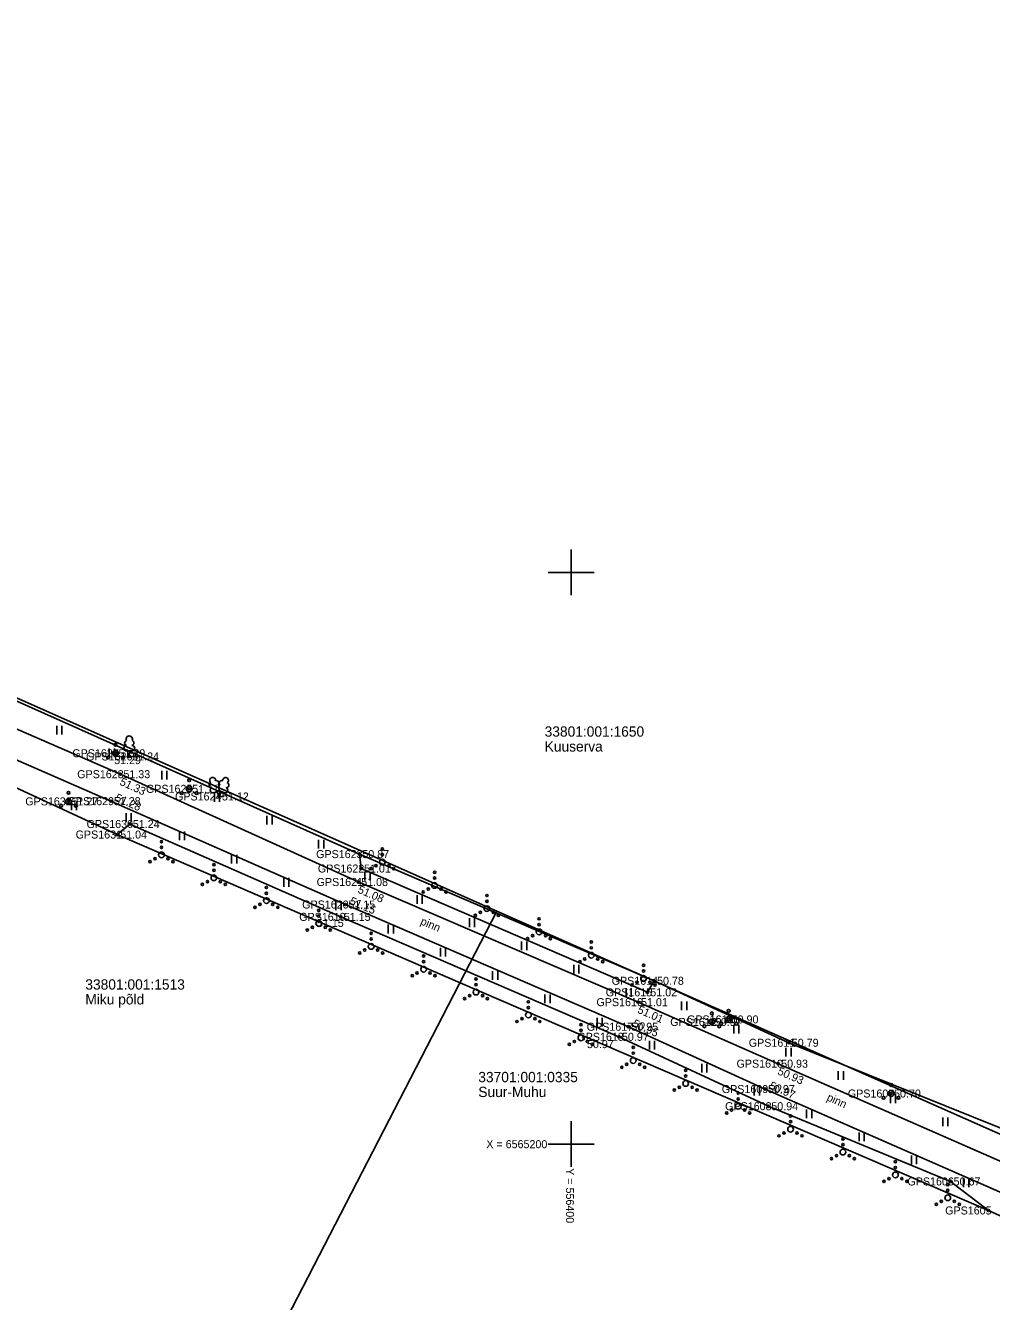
# Model space of a CAD drawing. Extents: x 551623 to 559850, y 6561220 to 6567135.
# Drawn here: x 556352.3 to 556436.7, y 6565186.2 to 6565297.8 of the extents above; entities that cross this region are included whole.
import ezdxf

# ---------------------------------------------------------------- set-up
doc = ezdxf.new("R2010")
doc.units = 0
for name, color, linetype in [('HALJASTUS', 7, 'Continuous'), ('KORGUS-EH2000', 7, 'Continuous'), ('MOOTKORG-EH2000', 7, 'Continuous'), ('MOOTMPUNKT', 7, 'Continuous'), ('MOOTNR', 7, 'Continuous'), ('MOOTPIIR', 7, 'Continuous'), ('PIIR', 7, 'Continuous'), ('PUU', 7, 'Continuous'), ('TEE', 7, 'Continuous'), ('VORK', 7, 'Continuous')]:
    doc.layers.add(name, color=color, linetype=linetype)

msp = doc.modelspace()

# ---------------------------------------------------------------- linework, layer by layer
at = {"layer": 'HALJASTUS'}
for p, q in [((556355.02, 6565236.58), (556355.02, 6565235.82)), ((556355.47, 6565236.58), (556355.47, 6565235.82)), ((556359.61, 6565234.61), (556359.61, 6565233.85)), ((556360.07, 6565234.61), (556360.07, 6565233.85)), ((556364.21, 6565232.64), (556364.21, 6565231.88)), ((556364.66, 6565232.64), (556364.66, 6565231.88)), ((556368.81, 6565230.68), (556368.81, 6565229.92)), ((556369.26, 6565230.68), (556369.26, 6565229.92)), ((556356.31, 6565229.95), (556356.31, 6565229.19)), ((556356.76, 6565229.95), (556356.76, 6565229.19)), ((556361.08, 6565228.95), (556361.08, 6565228.19)), ((556361.53, 6565228.95), (556361.53, 6565228.19)), ((556373.4, 6565228.71), (556373.4, 6565227.95)), ((556373.86, 6565228.71), (556373.86, 6565227.95)), ((556365.74, 6565227.34), (556365.74, 6565226.58)), ((556366.19, 6565227.34), (556366.19, 6565226.58)), ((556377.9, 6565226.6), (556377.9, 6565225.84)), ((556378.36, 6565226.6), (556378.36, 6565225.84)), ((556370.3, 6565225.3), (556370.3, 6565224.54)), ((556370.76, 6565225.3), (556370.76, 6565224.54)), ((556381.96, 6565223.82), (556381.96, 6565223.06)), ((556382.42, 6565223.82), (556382.42, 6565223.06)), ((556374.87, 6565223.27), (556374.87, 6565222.5)), ((556375.32, 6565223.27), (556375.32, 6565222.5)), ((556386.53, 6565221.78), (556386.53, 6565221.02)), ((556386.98, 6565221.78), (556386.98, 6565221.02)), ((556379.43, 6565221.23), (556379.43, 6565220.47)), ((556379.89, 6565221.23), (556379.89, 6565220.47)), ((556384, 6565219.19), (556384, 6565218.43)), ((556384.46, 6565219.19), (556384.46, 6565218.43)), ((556391.1, 6565219.75), (556391.1, 6565218.98)), ((556391.55, 6565219.75), (556391.55, 6565218.98)), ((556388.57, 6565217.15), (556388.57, 6565216.39)), ((556389.02, 6565217.15), (556389.02, 6565216.39)), ((556395.66, 6565217.71), (556395.66, 6565216.95)), ((556396.12, 6565217.71), (556396.12, 6565216.95)), ((556393.13, 6565215.12), (556393.13, 6565214.36)), ((556393.59, 6565215.12), (556393.59, 6565214.36)), ((556400.23, 6565215.67), (556400.23, 6565214.91)), ((556400.68, 6565215.67), (556400.68, 6565214.91)), ((556404.8, 6565213.64), (556404.8, 6565212.88)), ((556405.25, 6565213.64), (556405.25, 6565212.88)), ((556397.7, 6565213.08), (556397.7, 6565212.32)), ((556398.15, 6565213.08), (556398.15, 6565212.32)), ((556409.64, 6565212.47), (556409.64, 6565211.71)), ((556410.1, 6565212.47), (556410.1, 6565211.71)), ((556402.27, 6565211.04), (556402.27, 6565210.28)), ((556402.72, 6565211.04), (556402.72, 6565210.28)), ((556414.21, 6565210.44), (556414.21, 6565209.68)), ((556414.67, 6565210.44), (556414.67, 6565209.68)), ((556406.84, 6565209.02), (556406.84, 6565208.26)), ((556407.29, 6565209.02), (556407.29, 6565208.26)), ((556418.78, 6565208.41), (556418.78, 6565207.65)), ((556419.24, 6565208.41), (556419.24, 6565207.65)), ((556411.42, 6565207.02), (556411.42, 6565206.26)), ((556411.87, 6565207.02), (556411.87, 6565206.26)), ((556423.35, 6565206.38), (556423.35, 6565205.62)), ((556423.81, 6565206.38), (556423.81, 6565205.62)), ((556416, 6565205.02), (556416, 6565204.26)), ((556416.46, 6565205.02), (556416.46, 6565204.26)), ((556427.92, 6565204.35), (556427.92, 6565203.59)), ((556428.37, 6565204.35), (556428.37, 6565203.59)), ((556420.58, 6565203.02), (556420.58, 6565202.25)), ((556421.04, 6565203.02), (556421.04, 6565202.25)), ((556432.49, 6565202.32), (556432.49, 6565201.56)), ((556432.94, 6565202.32), (556432.94, 6565201.56)), ((556425.17, 6565201.01), (556425.17, 6565200.25)), ((556425.62, 6565201.01), (556425.62, 6565200.25)), ((556429.75, 6565199.01), (556429.75, 6565198.25)), ((556430.2, 6565199.01), (556430.2, 6565198.25)), ((556434.31, 6565196.98), (556434.31, 6565196.22)), ((556434.77, 6565196.98), (556434.77, 6565196.22))]:
    msp.add_line(p, q, dxfattribs=at)
for points in [[(556360.31, 6565227.07), (556361.41, 6565227.99), (556379.86, 6565219.87), (556404.18, 6565209.38), (556417.24, 6565203.31), (556433.18, 6565196.73), (556436.48, 6565194.19)], [(556381.48, 6565225.36), (556381.63, 6565224.1), (556406.66, 6565213.27), (556407.25, 6565214.28)]]:
    msp.add_lwpolyline(points, dxfattribs=at)
for centre, radius in [((556364.18, 6565226.44), 0.1), ((556364.18, 6565225.94), 0.1), ((556383.49, 6565225.81), 0.1), ((556363.18, 6565224.71), 0.1), ((556363.62, 6565224.96), 0.1), ((556364.18, 6565225.29), 0.25), ((556364.75, 6565224.96), 0.1), ((556365.18, 6565224.71), 0.1), ((556383.49, 6565224.66), 0.25), ((556383.49, 6565225.31), 0.1), ((556368.76, 6565224.44), 0.1), ((556368.76, 6565223.94), 0.1), ((556382.49, 6565224.09), 0.1), ((556382.93, 6565224.34), 0.1), ((556384.06, 6565224.34), 0.1), ((556384.49, 6565224.09), 0.1), ((556388.06, 6565223.77), 0.1), ((556367.76, 6565222.71), 0.1), ((556368.2, 6565222.96), 0.1), ((556368.76, 6565223.29), 0.25), ((556369.33, 6565222.96), 0.1), ((556369.76, 6565222.71), 0.1), ((556373.35, 6565222.44), 0.1), ((556388.06, 6565222.62), 0.25), ((556388.06, 6565223.27), 0.1), ((556373.35, 6565221.29), 0.25), ((556373.35, 6565221.94), 0.1), ((556387.06, 6565222.05), 0.1), ((556387.5, 6565222.3), 0.1), ((556388.63, 6565222.3), 0.1), ((556389.06, 6565222.05), 0.1), ((556392.63, 6565221.74), 0.1), ((556392.63, 6565221.24), 0.1), ((556372.35, 6565220.71), 0.1), ((556372.78, 6565220.96), 0.1), ((556373.91, 6565220.96), 0.1), ((556374.35, 6565220.71), 0.1), ((556377.93, 6565220.44), 0.1), ((556392.06, 6565220.26), 0.1), ((556392.63, 6565220.59), 0.25), ((556393.19, 6565220.26), 0.1), ((556377.93, 6565219.29), 0.25), ((556377.93, 6565219.94), 0.1), ((556391.63, 6565220.01), 0.1), ((556393.63, 6565220.01), 0.1), ((556397.19, 6565219.7), 0.1), ((556397.19, 6565219.2), 0.1), ((556376.93, 6565218.71), 0.1), ((556377.37, 6565218.96), 0.1), ((556378.5, 6565218.96), 0.1), ((556378.93, 6565218.71), 0.1), ((556382.51, 6565218.44), 0.1), ((556382.51, 6565217.94), 0.1), ((556396.19, 6565217.97), 0.1), ((556396.63, 6565218.22), 0.1), ((556397.19, 6565218.55), 0.25), ((556397.76, 6565218.22), 0.1), ((556398.19, 6565217.97), 0.1), ((556381.95, 6565216.97), 0.1), ((556382.51, 6565217.29), 0.25), ((556383.08, 6565216.97), 0.1), ((556401.76, 6565217.66), 0.1), ((556401.76, 6565217.16), 0.1), ((556381.51, 6565216.72), 0.1), ((556383.51, 6565216.72), 0.1), ((556387.1, 6565216.44), 0.1), ((556387.1, 6565215.94), 0.1), ((556400.76, 6565215.94), 0.1), ((556401.19, 6565216.19), 0.1), ((556401.76, 6565216.51), 0.25), ((556402.32, 6565216.19), 0.1), ((556402.76, 6565215.94), 0.1), ((556386.1, 6565214.72), 0.1), ((556386.53, 6565214.97), 0.1), ((556387.1, 6565215.29), 0.25), ((556387.66, 6565214.97), 0.1), ((556388.1, 6565214.72), 0.1), ((556406.33, 6565214.48), 0.25), ((556406.33, 6565215.63), 0.1), ((556406.33, 6565215.13), 0.1), ((556391.68, 6565213.29), 0.25), ((556391.68, 6565214.44), 0.1), ((556391.68, 6565213.94), 0.1), ((556405.33, 6565213.9), 0.1), ((556405.76, 6565214.15), 0.1), ((556406.89, 6565214.15), 0.1), ((556407.33, 6565213.9), 0.1), ((556390.68, 6565212.72), 0.1), ((556391.12, 6565212.97), 0.1), ((556392.25, 6565212.97), 0.1), ((556392.68, 6565212.72), 0.1), ((556396.26, 6565212.44), 0.1), ((556396.26, 6565211.29), 0.25), ((556396.26, 6565211.94), 0.1), ((556395.26, 6565210.72), 0.1), ((556395.7, 6565210.97), 0.1), ((556396.83, 6565210.97), 0.1), ((556397.26, 6565210.72), 0.1), ((556400.85, 6565210.44), 0.1), ((556400.28, 6565208.97), 0.1), ((556400.85, 6565209.29), 0.25), ((556400.85, 6565209.94), 0.1), ((556401.41, 6565208.97), 0.1), ((556399.85, 6565208.72), 0.1), ((556401.85, 6565208.72), 0.1), ((556405.43, 6565208.45), 0.1), ((556405.43, 6565207.95), 0.1), ((556404.86, 6565206.97), 0.1), ((556405.43, 6565207.3), 0.25), ((556405.99, 6565206.97), 0.1), ((556404.43, 6565206.72), 0.1), ((556406.43, 6565206.72), 0.1), ((556410.01, 6565206.45), 0.1), ((556410.01, 6565205.95), 0.1), ((556409.01, 6565204.72), 0.1), ((556409.45, 6565204.97), 0.1), ((556410.01, 6565205.3), 0.25), ((556410.58, 6565204.97), 0.1), ((556411.01, 6565204.72), 0.1), ((556414.6, 6565203.3), 0.25), ((556414.6, 6565204.45), 0.1), ((556414.6, 6565203.95), 0.1), ((556413.6, 6565202.72), 0.1), ((556414.03, 6565202.97), 0.1), ((556415.16, 6565202.97), 0.1), ((556415.6, 6565202.72), 0.1), ((556419.18, 6565202.45), 0.1), ((556419.18, 6565201.3), 0.25), ((556419.18, 6565201.95), 0.1), ((556418.18, 6565200.72), 0.1), ((556418.61, 6565200.97), 0.1), ((556419.74, 6565200.97), 0.1), ((556420.18, 6565200.72), 0.1), ((556423.76, 6565200.45), 0.1), ((556423.2, 6565198.98), 0.1), ((556423.76, 6565199.3), 0.25), ((556423.76, 6565199.95), 0.1), ((556424.33, 6565198.98), 0.1), ((556422.76, 6565198.73), 0.1), ((556424.76, 6565198.73), 0.1), ((556428.35, 6565198.45), 0.1), ((556428.35, 6565197.95), 0.1), ((556427.35, 6565196.73), 0.1), ((556427.78, 6565196.98), 0.1), ((556428.35, 6565197.3), 0.25), ((556428.91, 6565196.98), 0.1), ((556429.35, 6565196.73), 0.1), ((556432.93, 6565196.45), 0.1), ((556432.93, 6565195.95), 0.1), ((556431.93, 6565194.73), 0.1), ((556432.36, 6565194.98), 0.1), ((556432.93, 6565195.3), 0.25), ((556433.49, 6565194.98), 0.1), ((556433.93, 6565194.73), 0.1)]:
    msp.add_circle(centre, radius, dxfattribs=at)
at = {"layer": 'KORGUS-EH2000'}
for centre in [(556360.16, 6565234.18), (556360.59, 6565232.35), (556359.75, 6565229.99), (556360.31, 6565227.07), (556381.48, 6565225.36), (556381.38, 6565222.92), (556380.26, 6565220.95), (556379.86, 6565219.87), (556407.25, 6565214.28), (556405.85, 6565212.41), (556405, 6565210.26), (556404.18, 6565209.38), (556419.03, 6565208.86), (556418.1, 6565207.03), (556416.95, 6565204.81), (556417.24, 6565203.31), (556436.48, 6565194.19)]:
    msp.add_circle(centre, 0.1, dxfattribs=at)
at = {"layer": 'MOOTMPUNKT'}
for centre in [(556360.16, 6565234.18), (556361.36, 6565233.9), (556360.59, 6565232.35), (556366.6, 6565231.07), (556369.21, 6565230.4), (556356.05, 6565229.97), (556359.75, 6565229.99), (556361.41, 6565227.99), (556360.31, 6565227.07), (556381.48, 6565225.36), (556381.63, 6565224.1), (556381.38, 6565222.92), (556380.26, 6565220.95), (556379.86, 6565219.87), (556407.25, 6565214.28), (556405.85, 6565212.41), (556406.66, 6565213.27), (556405, 6565210.26), (556412.3, 6565210.68), (556413.77, 6565210.9), (556404.18, 6565209.38), (556419.03, 6565208.86), (556418.1, 6565207.03), (556416.95, 6565204.81), (556427.97, 6565204.42), (556417.24, 6565203.31), (556433.18, 6565196.73), (556436.48, 6565194.19)]:
    msp.add_circle(centre, 0.1, dxfattribs=at)
at = {"layer": 'MOOTPIIR'}
for points in [[(556444.3, 6565198.68), (556419.03, 6565208.86), (556407.25, 6565214.28), (556381.48, 6565225.36), (556332.64, 6565247.15), (556319.44, 6565253.29), (556278.3, 6565271.26)], [(556293.31, 6565257.46), (556317.81, 6565246.71), (556360.31, 6565227.07), (556390.3, 6565214.09), (556436.48, 6565194.19), (556449.65, 6565188.22)]]:
    msp.add_lwpolyline(points, dxfattribs=at)
at = {"layer": 'PIIR'}
for points in [[(556217.39, 6565298.59), (556213.87, 6565303.19), (556229.81, 6565311.25), (556335.44, 6565331.24), (556350.73, 6565342.07), (556507.54, 6565334), (556519.21, 6565368.05), (556548.5, 6565368.1), (556612.15, 6565380.04), (556615.14, 6565380.2), (556613.56, 6565366.23), (556611.32, 6565356.67), (556591.74, 6565273.2), (556570.09, 6565180.67), (556561.87, 6565145.74), (556557.67, 6565147.61), (556393.49, 6565220.36)], [(556206.35, 6565280.04), (556217.39, 6565298.59), (556393.49, 6565220.36), (556274.8, 6564990.28), (556228.34, 6565008.72), (556105.05, 6565057.69), (556140.52, 6565135.89), (556229.38, 6565104.35), (556274.08, 6565194.99), (556184.08, 6565232.1), (556196.52, 6565258.88), (556203.12, 6565272.11)], [(556393.49, 6565220.36), (556557.67, 6565147.61), (556561.87, 6565145.74), (556518.27, 6565016.8), (556485.25, 6564921.4), (556406.78, 6564699.5), (556400.89, 6564700.63), (556129.6, 6564752.43), (556228.34, 6565008.72), (556274.8, 6564990.28)]]:
    msp.add_lwpolyline(points, close=True, dxfattribs=at)
at = {"layer": 'PUU'}
for p, q in [((556361.6, 6565234.38), (556361.12, 6565234.38)), ((556361.36, 6565233.9), (556361.36, 6565234.38)), ((556361.74, 6565233.9), (556361.36, 6565233.9)), ((556368.77, 6565230.73), (556369.21, 6565230.91)), ((556369.21, 6565230.4), (556369.03, 6565230.84)), ((556369.21, 6565230.91), (556369.65, 6565230.73)), ((556369.21, 6565230.4), (556369.39, 6565230.84)), ((556369.59, 6565230.4), (556369.21, 6565230.4))]:
    msp.add_line(p, q, dxfattribs=at)
msp.add_lwpolyline([(556369.21, 6565231.4), (556369.19, 6565231.33), (556369.19, 6565231.31), (556369.2, 6565231.28), (556369.22, 6565231.24), (556369.23, 6565231.22), (556369.21, 6565231.19), (556369.19, 6565231.14), (556369.18, 6565231.11), (556369.19, 6565231.1), (556369.2, 6565231.07), (556369.23, 6565231.01), (556369.24, 6565230.99), (556369.23, 6565230.97), (556369.22, 6565230.93), (556369.21, 6565230.91)], dxfattribs=at)
for centre, radius in [((556360.16, 6565234.93), 0.125), ((556359.51, 6565233.81), 0.125), ((556360.16, 6565234.18), 0.25), ((556360.81, 6565233.81), 0.125), ((556366.6, 6565231.82), 0.125), ((556356.05, 6565230.72), 0.125), ((556365.95, 6565230.69), 0.125), ((556366.6, 6565231.07), 0.25), ((556367.25, 6565230.69), 0.125), ((556355.4, 6565229.59), 0.125), ((556356.05, 6565229.97), 0.25), ((556356.7, 6565229.59), 0.125), ((556412.3, 6565211.43), 0.125), ((556413.77, 6565211.65), 0.125), ((556411.65, 6565210.3), 0.125), ((556412.3, 6565210.68), 0.25), ((556412.95, 6565210.3), 0.125), ((556413.12, 6565210.53), 0.125), ((556413.77, 6565210.9), 0.25), ((556414.42, 6565210.53), 0.125), ((556427.97, 6565204.42), 0.25), ((556427.97, 6565205.17), 0.125), ((556427.32, 6565204.04), 0.125), ((556428.62, 6565204.04), 0.125)]:
    msp.add_circle(centre, radius, dxfattribs=at)
for centre, radius, start, end in [((556361.12, 6565234.62), 0.238, 90.0016, 269.3953), ((556361.19, 6565235.08), 0.233, 109.0217, 253.1415), ((556361.36, 6565235.42), 0.277, 332.5799, 207.4201), ((556361.53, 6565235.08), 0.233, 286.8508, 70.9859), ((556361.6, 6565234.62), 0.238, 270.6047, 89.9984), ((556368.57, 6565231.4), 0.224, 111.4304, 274.4987), ((556368.65, 6565231.81), 0.256, 111.5027, 232.5173), ((556368.65, 6565231.81), 0.256, 350.4856, 111.5002), ((556368.98, 6565231.56), 0.224, 308.5041, 111.5725), ((556369.21, 6565231.17), 0.237, 66.7655, 111.5015), ((556369.45, 6565231.56), 0.225, 67.7016, 230.5126), ((556369.78, 6565231.8), 0.256, 67.6168, 188.6314), ((556369.85, 6565231.39), 0.224, 264.6183, 67.6866), ((556369.78, 6565231.8), 0.256, 306.5997, 67.6143), ((556368.68, 6565230.96), 0.237, 111.5014, 291.5004), ((556369.74, 6565230.95), 0.237, 247.6166, 67.6155)]:
    msp.add_arc(centre, radius, start, end, dxfattribs=at)
at = {"layer": 'TEE'}
for points in [[(556212.52, 6565297.66), (556233.2, 6565288.81), (556257.43, 6565277.89), (556277.38, 6565268.88), (556295.26, 6565260.97), (556307.22, 6565255.62), (556319.32, 6565250.22), (556331.63, 6565244.87), (556340.73, 6565240.97), (556360.59, 6565232.35), (556381.38, 6565222.92), (556405.85, 6565212.41), (556418.1, 6565207.03), (556442.44, 6565196.36)], [(556563.78, 6565138.67), (556560.87, 6565140.85), (556553.17, 6565143.6), (556545.59, 6565147.01), (556535.18, 6565151.57), (556522.84, 6565156.96), (556502.18, 6565166.78), (556486.19, 6565174.09), (556471.01, 6565180.89), (556450.06, 6565190.45), (556440.99, 6565194.27), (556416.95, 6565204.81), (556405, 6565210.26), (556380.26, 6565220.95), (556359.75, 6565229.99), (556339.78, 6565238.7), (556330.66, 6565242.67), (556318.5, 6565248.07), (556306, 6565253.52), (556294.08, 6565258.94), (556276.19, 6565266.76), (556256.29, 6565275.58), (556232.17, 6565286.79), (556209.59, 6565295.96)]]:
    msp.add_lwpolyline(points, dxfattribs=at)
at = {"layer": 'VORK'}
for p, q in [((556400, 6565252), (556400, 6565248)), ((556398, 6565250), (556402, 6565250)), ((556400, 6565202), (556400, 6565198)), ((556398, 6565200), (556402, 6565200))]:
    msp.add_line(p, q, dxfattribs=at)

# ---------------------------------------------------------------- texts
at = {"layer": 'KORGUS-EH2000'}
for s, p in [(' 51.29', (556359.78, 6565233.23)), (' 51.04', (556360.31, 6565226.72)), (' 50.87', (556381.48, 6565225.01)), (' 51.15', (556377.51, 6565218.99)), (' 50.78', (556407.25, 6565213.93)), (' 50.97', (556401.12, 6565208.39)), (' 50.79', (556419.03, 6565208.51)), (' 50.94', (556417.24, 6565202.96))]:
    msp.add_text(s, height=0.7, dxfattribs=at).set_placement(p)
for s, rotation, p in [(' 51.33', 335.6082, (556360.23, 6565231.55)), (' 51.28', 336.2267, (556359.82, 6565230.15)), (' 51.08', 336.7632, (556381.04, 6565222.11)), (' 51.15', 336.6287, (556380.33, 6565221.11)), (' 51.01', 336.2742, (556405.5, 6565211.61)), (' 50.95', 335.4708, (556405.07, 6565210.42)), (' 50.93', 336.343, (556417.75, 6565206.23)), (' 50.97', 336.3229, (556417.02, 6565204.97))]:
    msp.add_text(s, height=0.7, rotation=rotation, dxfattribs=at).set_placement(p)
at = {"layer": 'MOOTKORG-EH2000'}
for s, p in [(' 51.29', (556360.16, 6565233.83)), (' 51.24', (556361.36, 6565233.55)), (' 51.33', (556360.59, 6565232)), (' 51.11', (556366.6, 6565230.72)), (' 51.27', (556356.05, 6565229.62)), (' 51.28', (556359.75, 6565229.64)), (' 51.12', (556369.21, 6565230.05)), (' 51.24', (556361.41, 6565227.64)), (' 51.04', (556360.31, 6565226.72)), (' 50.87', (556381.48, 6565225.01)), (' 51.01', (556381.63, 6565223.75)), (' 51.08', (556381.38, 6565222.57)), (' 51.15', (556379.86, 6565219.52)), (' 51.15', (556380.26, 6565220.6)), (' 50.78', (556407.25, 6565213.93)), (' 51.02', (556406.66, 6565212.92)), (' 51.01', (556405.85, 6565212.06)), (' 50.95', (556405, 6565209.91)), (' 50.97', (556412.3, 6565210.33)), (' 50.90', (556413.77, 6565210.55)), (' 50.97', (556404.18, 6565209.03)), (' 50.79', (556419.03, 6565208.51)), (' 50.93', (556418.1, 6565206.68)), (' 50.97', (556416.95, 6565204.46)), (' 50.70', (556427.97, 6565204.07)), (' 50.94', (556417.24, 6565202.96)), (' 50.67', (556433.18, 6565196.38))]:
    msp.add_text(s, height=0.7, dxfattribs=at).set_placement(p)
at = {"layer": 'MOOTNR'}
for s, p in [('GPS1627 ', (556356.38, 6565233.83)), ('GPS1626 ', (556357.58, 6565233.55)), ('GPS1628 ', (556356.81, 6565232)), ('GPS1625 ', (556362.82, 6565230.72)), ('GPS1632 ', (556352.27, 6565229.62)), ('GPS1629 ', (556355.97, 6565229.64)), ('GPS1624 ', (556365.36, 6565230.05)), ('GPS1630 ', (556357.63, 6565227.64)), ('GPS1631 ', (556356.67, 6565226.72)), ('GPS1623 ', (556377.7, 6565225.01)), ('GPS1622 ', (556377.85, 6565223.75)), ('GPS1621 ', (556377.74, 6565222.57)), ('GPS1619 ', (556376.22, 6565219.52)), ('GPS1620 ', (556376.48, 6565220.6)), ('GPS1614 ', (556403.54, 6565213.93)), ('GPS1615 ', (556403.02, 6565212.92)), ('GPS1616 ', (556402.21, 6565212.06)), ('GPS1617 ', (556401.36, 6565209.91)), ('GPS1612 ', (556408.66, 6565210.33)), ('GPS1613 ', (556410.13, 6565210.55)), ('GPS1618 ', (556400.54, 6565209.03)), ('GPS1611 ', (556415.53, 6565208.51)), ('GPS1610 ', (556414.46, 6565206.68)), ('GPS1609 ', (556413.17, 6565204.46)), ('GPS1607 ', (556424.19, 6565204.07)), ('GPS1608 ', (556413.46, 6565202.96)), ('GPS1606 ', (556429.4, 6565196.38)), ('GPS1605 ', (556432.7, 6565193.84))]:
    msp.add_text(s, height=0.7, dxfattribs=at).set_placement(p)
at = {"layer": 'PIIR'}
for s, p in [('33801:001:1650', (556397.68, 6565235.63)), ('Kuuserva', (556397.68, 6565234.33)), ('33801:001:1513', (556357.52, 6565213.51)), ('Miku põld', (556357.52, 6565212.21)), ('33701:001:0335', (556391.88, 6565205.41)), ('Suur-Muhu', (556391.88, 6565204.11))]:
    msp.add_text(s, height=0.9, dxfattribs=at).set_placement(p)
at = {"layer": 'TEE'}
for rotation, p in [(336.8446, (556386.76, 6565219.24)), (335.519, (556422.29, 6565203.85))]:
    msp.add_text('pinn', height=0.7, rotation=rotation, dxfattribs=at).set_placement(p)
at = {"layer": 'VORK'}
msp.add_text('X = 6565200', height=0.7, dxfattribs=at).set_placement((556392.58, 6565199.64))
msp.add_text('Y = 556400 ', height=0.7, rotation=270, dxfattribs=at).set_placement((556399.55, 6565197.89))

doc.saveas('drawing.dxf')
